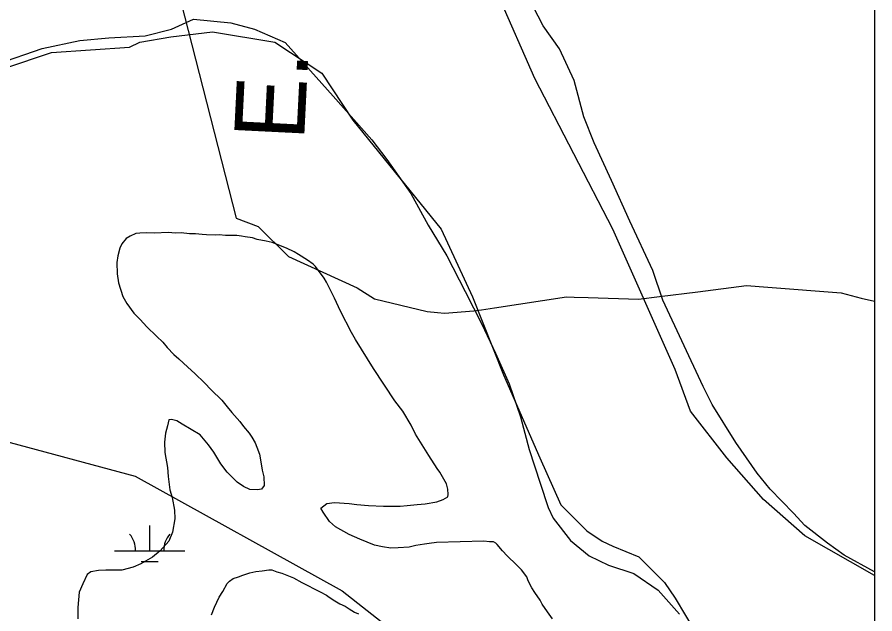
# Model space of a CAD drawing. Extents: x 3250478 to 3288318, y 788638 to 816472.
# Drawn here: x 3284850 to 3286073, y 797959 to 798809 of the extents above; entities that cross this region are included whole.
import ezdxf

# ---------------------------------------------------------------- set-up
doc = ezdxf.new("R2010")
doc.units = 0
for name, color, linetype in [('V-GRID-FRAM', 7, 'Continuous'), ('V-SITE-VEGE', 7, 'Continuous'), ('V-TOPO-BNDY', 7, 'Continuous'), ('V-TOPO-BNDY-IDEN', 7, 'Continuous'), ('V-TOPO-SHOR', 7, 'Continuous'), ('V-WETL-SWMP', 7, 'Continuous')]:
    doc.layers.add(name, color=color, linetype=linetype)

msp = doc.modelspace()

# ---------------------------------------------------------------- linework, layer by layer
at = {"layer": 'V-GRID-FRAM'}
msp.add_lwpolyline([(3254649.6, 812209.1), (3286070.1, 812200), (3286072.7, 794013.5), (3254636.4, 794022.7), (3254649.6, 812209.1)], dxfattribs=at)
at = {"layer": 'V-SITE-VEGE'}
for p, q in [((3286071.8, 800375.3), (3286072.1, 798018.7)), ((3285599.9, 798797.1), (3285403, 799175.1)), ((3285069.8, 798791.9), (3285101.4, 798806.5)), ((3285101.4, 798806.5), (3285154.3, 798801)), ((3285154.3, 798801), (3285188, 798791.9)), ((3285623.2, 798763.9), (3285599.9, 798797.1)), ((3284980.5, 798779.6), (3285032.1, 798782.7)), ((3285032.1, 798782.7), (3285069.8, 798791.9)), ((3285188, 798791.9), (3285231.7, 798772.9)), ((3284885.6, 798764.6), (3284939, 798775.8)), ((3284939, 798775.8), (3284980.5, 798779.6)), ((3285231.7, 798772.9), (3285300.4, 798696.4)), ((3284821.8, 798742.9), (3284885.6, 798764.6)), ((3285643.8, 798718.8), (3285623.2, 798763.9)), ((3285657.6, 798667), (3285643.8, 798718.8)), ((3285300.4, 798696.4), (3285329.8, 798663.3)), ((3285329.8, 798663.3), (3285355.5, 798634.6)), ((3285672.4, 798629.9), (3285657.6, 798667)), ((3285355.5, 798634.6), (3285377.1, 798606.4)), ((3285697.3, 798576.4), (3285672.4, 798629.9)), ((3285377.1, 798606.4), (3285411, 798557.7)), ((3285723.4, 798518.4), (3285697.3, 798576.4)), ((3285411, 798557.7), (3285435.7, 798512.8)), ((3285435.7, 798512.8), (3285462.4, 798469)), ((3285756.4, 798447.9), (3285723.4, 798518.4)), ((3285019.2, 798500.7), (3285010.7, 798497.2)), ((3285024.6, 798501.4), (3285019.2, 798500.7)), ((3285034.9, 798501.7), (3285024.6, 798501.4)), ((3285045.7, 798501.5), (3285034.9, 798501.7)), ((3285065.1, 798502.1), (3285045.7, 798501.5)), ((3285075.4, 798501.3), (3285065.1, 798502.1)), ((3285083.5, 798501.6), (3285075.4, 798501.3)), ((3285095.4, 798500.3), (3285083.5, 798501.6)), ((3285104.1, 798500.6), (3285095.4, 798500.3)), ((3285113.8, 798499.2), (3285104.1, 798500.6)), ((3285005.4, 798493.8), (3284999.2, 798486.1)), ((3285010.7, 798497.2), (3285005.4, 798493.8)), ((3285119.8, 798498.9), (3285113.8, 798499.2)), ((3285132.2, 798498.7), (3285119.8, 798498.9)), ((3285137.6, 798498.9), (3285132.2, 798498.7)), ((3285146.8, 798498.1), (3285137.6, 798498.9)), ((3285152.2, 798498.2), (3285146.8, 798498.1)), ((3285160.3, 798497.9), (3285152.2, 798498.2)), ((3285163, 798498), (3285160.3, 798497.9)), ((3285169.5, 798497.1), (3285163, 798498)), ((3285175, 798496.2), (3285169.5, 798497.1)), ((3285185.3, 798494.9), (3285175, 798496.2)), ((3285191.8, 798492.4), (3285185.3, 798494.9)), ((3285204.9, 798490.1), (3285191.8, 798492.4)), ((3285213.6, 798488.2), (3285204.9, 798490.1)), ((3285233.8, 798480.1), (3285213.6, 798488.2)), ((3284996.1, 798480), (3284993.2, 798469.1)), ((3284999.2, 798486.1), (3284996.1, 798480)), ((3285244.8, 798474.5), (3285233.8, 798480.1)), ((3284993.2, 798469.1), (3284991.9, 798459.4)), ((3285250.8, 798470.9), (3285244.8, 798474.5)), ((3285264, 798462.7), (3285250.8, 798470.9)), ((3285462.4, 798469), (3285488.7, 798418)), ((3284991.9, 798459.4), (3284992.3, 798443.2)), ((3285271.8, 798457), (3285264, 798462.7)), ((3285275.1, 798453.8), (3285271.8, 798457)), ((3285287.5, 798437.4), (3285275.1, 798453.8)), ((3284992.3, 798443.2), (3284994.3, 798430.3)), ((3285770.3, 798405.7), (3285756.4, 798447.9)), ((3284994.3, 798430.3), (3285000.3, 798411)), ((3285290.9, 798431.6), (3285287.5, 798437.4)), ((3285302.4, 798408.7), (3285290.9, 798431.6)), ((3285488.7, 798418), (3285512.4, 798371.6)), ((3285000.3, 798411), (3285006, 798400.9)), ((3285311, 798390.1), (3285302.4, 798408.7)), ((3285827.8, 798282.7), (3285770.3, 798405.7)), ((3285006, 798400.9), (3285016.2, 798387.2)), ((3285326.5, 798359.7), (3285311, 798390.1)), ((3285016.2, 798387.2), (3285025.1, 798378.3)), ((3285025.1, 798378.3), (3285034.6, 798367.7)), ((3285034.6, 798367.7), (3285048.5, 798354.7)), ((3285512.4, 798371.6), (3285531.9, 798330.1)), ((3285048.5, 798354.7), (3285057.4, 798345.7)), ((3285332.2, 798349.6), (3285326.5, 798359.7)), ((3285057.4, 798345.7), (3285063.5, 798338.4)), ((3285357.8, 798308.3), (3285332.2, 798349.6)), ((3285063.5, 798338.4), (3285073, 798328.4)), ((3285531.9, 798330.1), (3285551.5, 798286.6)), ((3285073, 798328.4), (3285080.2, 798322.1)), ((3285080.2, 798322.1), (3285093, 798310.1)), ((3285093, 798310.1), (3285103, 798301.2)), ((3285388.3, 798262.2), (3285357.8, 798308.3)), ((3285103, 798301.2), (3285116.9, 798288.1)), ((3285116.9, 798288.1), (3285126.4, 798278.1)), ((3285551.5, 798286.6), (3285567.6, 798239.4)), ((3285840.7, 798257.2), (3285827.8, 798282.7)), ((3285126.4, 798278.1), (3285141.4, 798263.4)), ((3285141.4, 798263.4), (3285149.3, 798253.9)), ((3285399.6, 798247.4), (3285388.3, 798262.2)), ((3285874.3, 798202.9), (3285840.7, 798257.2)), ((3285149.3, 798253.9), (3285156, 798245.5)), ((3285156, 798245.5), (3285167.2, 798232.9)), ((3285411.5, 798227.8), (3285399.6, 798247.4)), ((3285066.1, 798235.2), (3285064.2, 798226.6)), ((3285069.9, 798235.9), (3285066.1, 798235.2)), ((3285077.5, 798234), (3285069.9, 798235.9)), ((3285085.2, 798228.8), (3285077.5, 798234)), ((3285167.2, 798232.9), (3285172.3, 798225.5)), ((3285567.6, 798239.4), (3285579.7, 798193.1)), ((3285064.2, 798226.6), (3285061.3, 798216.2)), ((3285110.5, 798213.9), (3285085.2, 798228.8)), ((3285172.3, 798225.5), (3285180.7, 798216)), ((3285417.8, 798215), (3285411.5, 798227.8)), ((3285061.3, 798216.2), (3285060, 798203.2)), ((3285122.8, 798199.7), (3285110.5, 798213.9)), ((3285180.7, 798216), (3285184.6, 798210.7)), ((3285184.6, 798210.7), (3285189.2, 798202.2)), ((3285436.6, 798184.2), (3285417.8, 798215)), ((3285060, 798203.2), (3285060.5, 798188.6)), ((3285130.1, 798189.1), (3285122.8, 798199.7)), ((3285189.2, 798202.2), (3285191.5, 798196.3)), ((3285191.5, 798196.3), (3285195.1, 798186.2)), ((3285905, 798159.2), (3285874.3, 798202.9)), ((3285060.5, 798188.6), (3285064.3, 798167.1)), ((3285140.4, 798172.6), (3285130.1, 798189.1)), ((3285195.1, 798186.2), (3285196.9, 798178.1)), ((3285448.5, 798165.7), (3285436.6, 798184.2)), ((3285579.7, 798193.1), (3285595.3, 798144.9)), ((3285149.4, 798160.5), (3285140.4, 798172.6)), ((3285196.9, 798178.1), (3285199, 798163.6)), ((3285064.3, 798167.1), (3285065.3, 798154.2)), ((3285163.3, 798146.3), (3285149.4, 798160.5)), ((3285199, 798163.6), (3285201.4, 798153.9)), ((3285452.4, 798160.4), (3285448.5, 798165.7)), ((3285462.1, 798143.9), (3285452.4, 798160.4)), ((3285923.4, 798136.4), (3285905, 798159.2)), ((3285065.3, 798154.2), (3285067.5, 798135.3)), ((3285172.7, 798140.1), (3285163.3, 798146.3)), ((3285201.4, 798153.9), (3285201.8, 798141.5)), ((3285067.5, 798135.3), (3285071, 798124.7)), ((3285181.4, 798136.1), (3285172.7, 798140.1)), ((3285192.3, 798135.3), (3285181.4, 798136.1)), ((3285198.2, 798136.6), (3285192.3, 798135.3)), ((3285201.8, 798141.5), (3285198.2, 798136.6)), ((3285464, 798136.4), (3285462.1, 798143.9)), ((3285464.2, 798128.9), (3285464, 798136.4)), ((3285595.3, 798144.9), (3285607, 798110.2)), ((3285956.9, 798102), (3285923.4, 798136.4)), ((3285071, 798124.7), (3285074.3, 798106.4)), ((3285448.3, 798118.1), (3285457.4, 798121.6)), ((3285457.4, 798121.6), (3285463.7, 798125.6)), ((3285463.7, 798125.6), (3285464.2, 798128.9)), ((3285282.7, 798109.4), (3285291.2, 798116.1)), ((3285286.1, 798103.5), (3285282.7, 798109.4)), ((3285291.2, 798116.1), (3285302.5, 798117.5)), ((3285302.5, 798117.5), (3285323, 798116)), ((3285323, 798116), (3285333.9, 798114.7)), ((3285333.9, 798114.7), (3285350.7, 798113)), ((3285350.7, 798113), (3285372.3, 798112.1)), ((3285372.3, 798112.1), (3285381.5, 798112.3)), ((3285381.5, 798112.3), (3285396.1, 798112.2)), ((3285396.1, 798112.2), (3285405.8, 798113.1)), ((3285405.8, 798113.1), (3285420.3, 798114.6)), ((3285420.3, 798114.6), (3285431.6, 798115.5)), ((3285431.6, 798115.5), (3285448.3, 798118.1)), ((3285607, 798110.2), (3285614, 798095.2)), ((3285074.3, 798106.4), (3285074.6, 798094)), ((3285295.2, 798090.3), (3285286.1, 798103.5)), ((3285972.7, 798084.7), (3285956.9, 798102)), ((3285074.6, 798094), (3285071.4, 798075)), ((3285303.5, 798082.5), (3285295.2, 798090.3)), ((3285614, 798095.2), (3285638.8, 798063)), ((3286005.4, 798059.3), (3285972.7, 798084.7)), ((3285071.4, 798075), (3285065.9, 798062.4)), ((3285323.3, 798071.7), (3285303.5, 798082.5)), ((3285065.9, 798062.4), (3285053.9, 798048.5)), ((3285338.6, 798065.1), (3285323.3, 798071.7)), ((3285359.4, 798056.6), (3285338.6, 798065.1)), ((3285447.9, 798060.3), (3285437.1, 798058.9)), ((3285515.3, 798062.3), (3285447.9, 798060.3)), ((3285523.5, 798061.5), (3285515.3, 798062.3)), ((3285528.9, 798061.1), (3285523.5, 798061.5)), ((3285532.2, 798059.6), (3285528.9, 798061.1)), ((3285638.8, 798063), (3285665.3, 798041.5)), ((3285053.9, 798048.5), (3285042.8, 798039.5)), ((3285370.8, 798054.2), (3285359.4, 798056.6)), ((3285382.7, 798052.4), (3285370.8, 798054.2)), ((3285393, 798052.7), (3285382.7, 798052.4)), ((3285408.6, 798053.7), (3285393, 798052.7)), ((3285418.3, 798056.2), (3285408.6, 798053.7)), ((3285430.6, 798058.2), (3285418.3, 798056.2)), ((3285437.1, 798058.9), (3285430.6, 798058.2)), ((3285534.4, 798057.5), (3285532.2, 798059.6)), ((3285541.7, 798048.5), (3285534.4, 798057.5)), ((3285548.4, 798041.2), (3285541.7, 798048.5)), ((3286029.2, 798042.2), (3286005.4, 798059.3)), ((3285042.8, 798039.5), (3285026.3, 798029.9)), ((3285561.7, 798028.6), (3285548.4, 798041.2)), ((3285665.3, 798041.5), (3285693.1, 798028.1)), ((3286072.1, 798018.7), (3286029.2, 798042.2)), ((3285015.1, 798025.2), (3284999, 798020.9)), ((3285026.3, 798029.9), (3285015.1, 798025.2)), ((3285569, 798021.3), (3285561.7, 798028.6)), ((3285693.1, 798028.1), (3285729, 798016)), ((3284949.5, 798014.6), (3284943.4, 798001.4)), ((3284954.8, 798018.5), (3284949.5, 798014.6)), ((3284965.6, 798020.5), (3284954.8, 798018.5)), ((3284976.4, 798020.8), (3284965.6, 798020.5)), ((3284993.1, 798020.8), (3284976.4, 798020.8)), ((3284999, 798020.9), (3284993.1, 798020.8)), ((3285157.7, 798008.9), (3285165.2, 798011.3)), ((3285165.2, 798011.3), (3285171.6, 798013.7)), ((3285171.6, 798013.7), (3285181.7, 798017.2)), ((3285181.7, 798017.2), (3285190.3, 798019.1)), ((3285190.3, 798019.1), (3285199, 798019.9)), ((3285199, 798019.9), (3285208.6, 798021.3)), ((3285208.6, 798021.3), (3285213, 798021.4)), ((3285213, 798021.4), (3285220.1, 798018.4)), ((3285220.1, 798018.4), (3285227.1, 798016.4)), ((3285227.1, 798016.4), (3285243.6, 798009.9)), ((3285576.3, 798011.2), (3285569, 798021.3)), ((3285578.6, 798005.9), (3285576.3, 798011.2)), ((3285729, 798016), (3285763.7, 797992.2)), ((3284943.4, 798001.4), (3284938.4, 797989.4)), ((3285143.1, 797990.7), (3285149.3, 798001.7)), ((3285149.3, 798001.7), (3285152.4, 798005)), ((3285152.4, 798005), (3285157.7, 798008.9)), ((3285243.6, 798009.9), (3285255.6, 798003.2)), ((3285255.6, 798003.2), (3285282, 797990)), ((3285583.8, 797995.8), (3285578.6, 798005.9)), ((3284938.4, 797989.4), (3284936.3, 797967.7)), ((3285138, 797982.4), (3285143.1, 797990.7)), ((3285282, 797990), (3285290.7, 797985.4)), ((3285587.8, 797988.9), (3285583.8, 797995.8)), ((3285595.6, 797978.3), (3285587.8, 797988.9)), ((3285763.7, 797992.2), (3285794.1, 797958.1)), ((3285131.4, 797968.2), (3285138, 797982.4)), ((3285290.7, 797985.4), (3285294.6, 797982.2)), ((3285294.6, 797982.2), (3285302.9, 797977.1)), ((3285302.9, 797977.1), (3285310, 797973)), ((3285598.5, 797972.4), (3285595.6, 797978.3)), ((3284936.3, 797967.7), (3284936.3, 797951.5)), ((3285126.8, 797957.2), (3285131.4, 797968.2)), ((3285310, 797973), (3285317.7, 797969.4)), ((3285317.7, 797969.4), (3285323.2, 797965.8)), ((3285323.2, 797965.8), (3285330.9, 797961.2)), ((3285605.9, 797961.3), (3285598.5, 797972.4)), ((3285330.9, 797961.2), (3285336.4, 797958.6)), ((3285613.2, 797951.3), (3285605.9, 797961.3))]:
    msp.add_line(p, q, dxfattribs=at)
at = {"layer": 'V-TOPO-BNDY'}
for p, q in [((3285083.1, 798831.2), (3285162.2, 798522.5)), ((3285162.2, 798522.5), (3285193.5, 798510.8)), ((3285193.5, 798510.8), (3285236.6, 798467.9)), ((3285236.6, 798467.9), (3285334.8, 798423.4)), ((3285820.4, 798417.9), (3285889.9, 798426.7)), ((3285889.9, 798426.7), (3285920.3, 798424.3)), ((3285334.8, 798423.4), (3285359.3, 798407.6)), ((3285765.6, 798411), (3285820.4, 798417.9)), ((3285920.3, 798424.3), (3286024.5, 798416.3)), ((3286024.5, 798416.3), (3286053.3, 798408.8)), ((3285359.3, 798407.6), (3285434.4, 798389.8)), ((3285530.6, 798394.9), (3285633.3, 798410.5)), ((3285633.3, 798410.5), (3285643.9, 798410.3)), ((3285643.9, 798410.3), (3285663.9, 798409.6)), ((3285663.9, 798409.6), (3285735.6, 798407.2)), ((3285735.6, 798407.2), (3285765.6, 798411)), ((3286053.3, 798408.8), (3286072.1, 798404.6)), ((3285459, 798387.1), (3285501.1, 798390.5)), ((3285501.1, 798390.5), (3285511.7, 798392.1)), ((3285511.7, 798392.1), (3285530.6, 798394.9)), ((3285434.4, 798389.8), (3285449.1, 798388.2)), ((3285449.1, 798388.2), (3285459, 798387.1))]:
    msp.add_line(p, q, dxfattribs=at)
at = {"layer": 'V-TOPO-SHOR'}
for points in [[(3285698.9, 798506.9), (3285587.8, 798721.8), (3285535.9, 798840.3)], [(3284832, 798736.6), (3284898.7, 798758.8), (3285009.8, 798766.3), (3285024.7, 798773.7), (3285069.1, 798781.1), (3285128.4, 798788.5), (3285217.3, 798773.7), (3285284, 798729.2), (3285328.4, 798662.5), (3285454.4, 798506.9), (3285498.9, 798410.6), (3285543.3, 798299.5), (3285595.2, 798180.9), (3285624.8, 798114.2), (3285661.9, 798077.2), (3285684.1, 798062.4), (3285698.9, 798055), (3285736, 798040.1), (3285773, 798003.1), (3285787.8, 797980.9), (3285832.3, 797906.8)], [(3286072.1, 798013.2), (3285973.1, 798069.8), (3285913.8, 798121.6), (3285861.9, 798180.9), (3285810, 798247.6), (3285787.8, 798306.9), (3285698.9, 798506.9)]]:
    msp.add_lwpolyline(points, dxfattribs=at)
at = {"layer": 'V-WETL-SWMP'}
for p, q in [((3284827.6, 798206.4), (3285018.2, 798154.7)), ((3285018.2, 798154.7), (3285313.4, 797991.4)), ((3285038.8, 798048.7), (3285038.8, 798084.7)), ((3284988.8, 798048.7), (3285088.8, 798048.7)), ((3285026.7, 798033.3), (3285050.7, 798033.3)), ((3285313.4, 797991.4), (3285541.5, 797812.6))]:
    msp.add_line(p, q, dxfattribs=at)
for centre, start, end in [((3284983.5, 798049.2), 359.2115, 40.7552), ((3285094, 798049.2), 139.2115, 180.7552)]:
    msp.add_arc(centre, 35.2, start, end, dxfattribs=at)

# ---------------------------------------------------------------- texts
at = {"layer": 'V-TOPO-BNDY-IDEN'}
msp.add_text('E.  ', height=100, rotation=87.1491, dxfattribs=at).set_placement((3285258.8, 798632.5))

doc.saveas('drawing.dxf')
